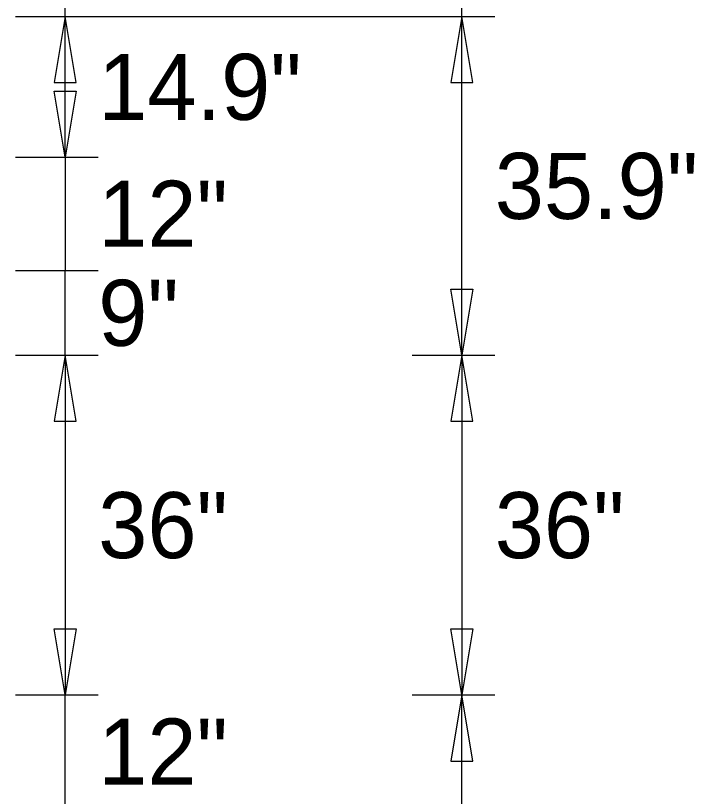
# Model space of a CAD drawing. Extents: x 2149961 to 2150220, y 145114 to 145240.
# Drawn here: x 2149999.66 to 2150005.65, y 145226.37 to 145233.27 of the extents above; entities that cross this region are included whole.
import ezdxf

# ---------------------------------------------------------------- set-up
doc = ezdxf.new("R2010")
doc.units = 0
doc.layers.add('GSDIMS', color=7, linetype='Continuous')

msp = doc.modelspace()

# ---------------------------------------------------------------- linework, layer by layer
at = {"layer": 'GSDIMS'}
for p, q in [((2150000.0963, 145233.2618), (2150000.0963, 145234.0124)), ((2150003.5963, 145233.2618), (2150003.5963, 145234.0124)), ((2149999.6588, 145233.2619), (2150000.3879, 145233.2619)), ((2149999.6588, 145233.2619), (2150003.1588, 145233.2619)), ((2149999.6588, 145233.2618), (2150000.3879, 145233.2618)), ((2149999.6588, 145233.2618), (2150003.1588, 145233.2618)), ((2150000.0963, 145232.0202), (2150000.0963, 145233.2619)), ((2150003.1588, 145233.2619), (2150003.8879, 145233.2619)), ((2150003.1588, 145233.2618), (2150003.8879, 145233.2618)), ((2150003.5963, 145230.2702), (2150003.5963, 145233.2619)), ((2149999.6588, 145232.0202), (2150000.3879, 145232.0202)), ((2149999.6588, 145232.0202), (2150000.3879, 145232.0202)), ((2150000.0963, 145232.0202), (2150000.0963, 145231.0202)), ((2149999.6588, 145231.0202), (2150000.3879, 145231.0202)), ((2149999.6588, 145231.0202), (2150000.3879, 145231.0202)), ((2150000.0963, 145230.2702), (2150000.0963, 145231.0202)), ((2149999.6588, 145230.2702), (2150000.3879, 145230.2702)), ((2149999.6588, 145230.2702), (2150000.3879, 145230.2702)), ((2150000.0963, 145230.2702), (2150000.0963, 145227.2701)), ((2150003.1588, 145230.2702), (2150003.8879, 145230.2702)), ((2150003.1588, 145230.2702), (2150003.8879, 145230.2702)), ((2150003.5963, 145230.2702), (2150003.5963, 145227.2701)), ((2149999.6588, 145227.2701), (2150000.3879, 145227.2701)), ((2149999.6588, 145227.2701), (2150000.3879, 145227.2701)), ((2150000.0963, 145226.2702), (2150000.0963, 145227.2701)), ((2150003.1588, 145227.2701), (2150003.8879, 145227.2701)), ((2150003.1588, 145227.2701), (2150003.8879, 145227.2701)), ((2150003.5963, 145216.7618), (2150003.5963, 145227.2701))]:
    msp.add_line(p, q, dxfattribs=at)
for points in [[(2150000.0963, 145233.2619), (2149999.999, 145232.6786), (2150000.1935, 145232.6786)], [(2150003.5963, 145233.2619), (2150003.499, 145232.6786), (2150003.6935, 145232.6786)], [(2150000.0963, 145232.0202), (2149999.999, 145232.6035), (2150000.1935, 145232.6035)], [(2150003.5963, 145230.2702), (2150003.499, 145230.8535), (2150003.6935, 145230.8535)], [(2150000.0963, 145230.2702), (2149999.999, 145229.6869), (2150000.1935, 145229.6869)], [(2150003.5963, 145230.2702), (2150003.499, 145229.6869), (2150003.6935, 145229.6869)], [(2150000.0963, 145227.2701), (2149999.999, 145227.8534), (2150000.1935, 145227.8534)], [(2150003.5963, 145227.2701), (2150003.499, 145227.8534), (2150003.6935, 145227.8534)], [(2150003.5963, 145227.2701), (2150003.499, 145226.6868), (2150003.6935, 145226.6868)]]:
    msp.add_lwpolyline(points, close=True, dxfattribs=at)

# ---------------------------------------------------------------- texts
for s, p in [('14.9"', (2150000.388, 145232.3493)), ('35.9"', (2150003.888, 145231.4744)), ('12"', (2150000.388, 145231.2285)), ('9"', (2150000.388, 145230.3535)), ('36"', (2150000.388, 145228.4785)), ('36"', (2150003.888, 145228.4785)), ('12"', (2150000.388, 145226.4785))]:
    msp.add_text(s, height=0.58333, dxfattribs=at).set_placement(p)

doc.saveas('drawing.dxf')
